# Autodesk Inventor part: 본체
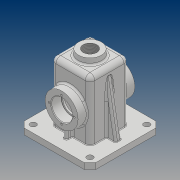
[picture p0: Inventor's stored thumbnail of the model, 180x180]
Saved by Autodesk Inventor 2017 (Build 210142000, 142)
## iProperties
Part Number: 본체
Material: 일반
Document SubType Name: Modeling
Designer: 20
Density: 1 g/cm^3
Appearance: 기본값
Mass: 292.152 g
Surface Area: 897.772 cm^2
Volume: 292.152 cm^3
Author: 20
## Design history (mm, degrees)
sketch "스케치1"
  geometry: L1 (-32.5, 32.5)-(32.5, 32.5); L2 (32.5, 32.5)-(32.5, -32.5); L3 (32.5, -32.5)-(-32.5, -32.5); L4 (-32.5, -32.5)-(-32.5, 32.5); L5 (-32.5, 32.5)-(32.5, -32.5); L6 (32.5, 32.5)-(-32.5, -32.5); 1 further point
  constraints: 12 end point, 2 midpoint, 2 parallel, 1 horizontal, 1 perpendicular
  dimensions: "d0" = 65 distance of L2.end L3.end; "d1" = 65 distance of L1.end L2.end
extrude "돌출1" new body sketch "스케치1" distance "d2" = 110; taper "d3" = 0 deg
fillet "모깎기1" dims "d4" = 8
feature "쉘1" dims "d5" = 5
sketch "스케치2"
  geometry: L1 (60, -60)-(-60, -60); L2 (-60, -60)-(-60, 60); L3 (-60, 60)-(60, 60); L4 (60, 60)-(60, -60); L5 (60, -60)-(-60, 60); L6 (-60, -60)-(60, 60); L7 (24.5, -27.5)-(-24.5, -27.5) reference; L8 (-27.5, -24.5)-(-27.5, 24.5) reference; L9 (-24.5, 27.5)-(24.5, 27.5) reference; L10 (27.5, 24.5)-(27.5, -24.5) reference; L11 (-32.5, 24.5)-(-32.5, -24.5) reference; L12 (-24.5, -32.5)-(24.5, -32.5) reference; L13 (32.5, -24.5)-(32.5, 24.5) reference; L14 (24.5, 32.5)-(-24.5, 32.5) reference; A1 r 3 centre (24.5, -24.5) between (24.5, -27.5) and (27.5, -24.5) reference; A2 r 3 centre (-24.5, -24.5) between (-27.5, -24.5) and (-24.5, -27.5) reference; A3 r 3 centre (-24.5, 24.5) between (-24.5, 27.5) and (-27.5, 24.5) reference; A4 r 3 centre (24.5, 24.5) between (27.5, 24.5) and (24.5, 27.5) reference; A5 r 8 centre (-24.5, 24.5) between (-24.5, 32.5) and (-32.5, 24.5) reference; A6 r 8 centre (-24.5, -24.5) between (-32.5, -24.5) and (-24.5, -32.5) reference; A7 r 8 centre (24.5, -24.5) between (24.5, -32.5) and (32.5, -24.5) reference; A8 r 8 centre (24.5, 24.5) between (32.5, 24.5) and (24.5, 32.5) reference; 1 further point
  constraints: 12 end point, 2 midpoint, 2 parallel, 1 horizontal, 1 perpendicular
  dimensions: "d6" = 120 distance of L2.end L3.end; "d7" = 120 distance of L1.end L2.end
extrude "돌출2" join sketch "스케치2" distance "d8" = 10; taper "d9" = 0 deg
chamfer "모따기1" distance "d10" = 10; stored, may be unused: second distance "d11" = 2, angle "d12" = 45 deg
sketch "스케치3"
  geometry: L1 (-25.5, -102)-(74.5, -102) reference; C1 r 27.5 at (24.5, -47); 2 further points
  constraints: 1 centre point, 1 midpoint, 1 vertical alignment
  dimensions: "d13" = 55 diameter of C1; "d14" = 55 distance from line of L1 C1.centre
extrude "돌출3" join sketch "스케치3" distance "d15" = 15; taper "d16" = 0 deg
sketch "스케치4"
  geometry: L1 (24.5, 47)-(24.5, 12.49) reference; L2 (-24.5, 47)-(24.5, 47) reference; L3 (-24.5, 12.49)-(-24.5, 47) reference; C1 r 17.5 at (0, 0); A1 r 27.5 centre (0, 0) between (24.5, 12.49) and (-24.5, 12.49) reference; A2 r 27.5 centre (0, 0) between (-24.5, 12.49) and (24.5, 12.49) reference; 1 further point
  constraints: 1 centre point, 1 coincident
  dimensions: "d17" = 35 diameter of C1
extrude "돌출4" cut sketch "스케치4" distance "d18" = 17; taper "d19" = 0 deg
sketch "스케치5"
  geometry: C1 r 15 at (0, 0); C2 r 17.5 at (0, 0) reference; 1 further point
  constraints: 1 centre point, 1 concentric
  dimensions: "d20" = 30 diameter of C1
extrude "돌출5" cut sketch "스케치5" distance "d21" = 3; taper "d22" = 0 deg
sketch "스케치6"
  geometry: C1 r 17.5 at (0, 0) reference; 2 further points
  constraints: 1 horizontal alignment
  dimensions: "d23" = 21 distance of C1.centre point (-21, 0)
hole "구멍1" sketch "스케치6" at (-21, 0) diameter "d24" = 3.242; stored, may be unused: countersink angle "d28" = 90 deg, drill point angle "d30" = 118 deg; dims "d25" = 8, "d26" = 4, "d27" = 2, "d29" = 10
node "작업 평면1"
sketch "스케치7"
  geometry: C1 r 20 at (0, 0); 1 further point
  constraints: 1 centre point, 1 coincident
  dimensions: "d35" = 40 diameter of C1
extrude "돌출6" join sketch "스케치7" stored distance "d36" = 10; taper "d37" = 0 deg
feature "면 기울기1" dims angle "d38" = 5 deg
hole "구멍2" diameter "d41" = 22.835; stored, may be unused: countersink angle "d45" = 90 deg, drill point angle "d47" = 118 deg; dims "d39" = 10, "d40" = 10, "d42" = 50, "d43" = 4, "d44" = 2, "d46" = 59.3
sketch "스케치8"
  geometry: L1 (-3, -27.5)-(3, -27.5); L2 (3, -27.5)-(3, -42.5); L3 (3, -42.5)-(-3, -42.5); L4 (-3, -42.5)-(-3, -27.5); L5 (-24.5, -27.5)-(24.5, -27.5) reference; 1 further point
  constraints: 8 end point, 2 parallel, 1 horizontal, 1 perpendicular
  dimensions: "d48" = 6 distance of L2.end L3.end; "d49" = 0 distance between parallel lines of L1 L5; "d50" = 3 distance from line of point (0, 0) L4; "d51" = 15 distance between parallel lines of L3 L5
extrude "돌출7" join sketch "스케치8" stored distance "d52" = 10; taper "d53" = 0 deg
sketch "스케치9"
  geometry: C1 r 5 at (-47.5, 47.5); 1 further point
  constraints: 1 centre point
  dimensions: "d54" = 10 diameter of C1; "d55" = 47.5 horizontal distance of point (0, 0) C1.centre; "d56" = 47.5 horizontal distance of point (0, 0) C1.centre
extrude "돌출8" cut sketch "스케치9" distance "d57" = 10; taper "d58" = 0 deg
sketch "스케치10"
  geometry: L1 (37.42, 70)-(48, 10); L2 (60, 10)-(50, 10) reference; L3 (-50, 10)-(50, 10) reference; L4 (60, 0)-(60, 10) reference; 1 further point
  constraints: 2 end point, 1 point on line
  dimensions: "d59" = 10 deg angle of L1 L4; "d60" = 12 distance of L1.end L2.start; "d61" = 60 vertical distance of L1.start L1.end
feature "리브1" sketch "스케치10" dims "d62" = 1, "d63" = 10, "d64" = 0, "d65" = 0, "d66" = 1, "d67" = 1
fillet "모깎기2" dims "d68" = 3
fillet "모깎기3" dims "d69" = 0.3
fillet "모깎기4" dims "d70" = 3
fillet "모깎기5" dims "d71" = 3
fillet "모깎기6" dims "d72" = 3
fillet "모깎기7" dims "d73" = 3
fillet "모깎기8" dims "d74" = 3
fillet "모깎기9" dims "d75" = 1
fillet "모깎기10" dims "d76" = 3
fillet "모깎기11" dims "d77" = 3
node "작업 평면2"
sketch "스케치11"
  geometry: L1 (57, 0)-(57, 91) reference; L2 (43.625, -18)-(5.375, -18) reference; 2 further points
  constraints: 1 other
  dimensions: "d79" = 32.5 distance from line of point (24.5, 8) L1; "d80" = 26 distance from line of point (24.5, 8) L2
feature "엠보싱1" sketch "스케치11" dims "d6" = 120, "d7" = 120, "d81" = 0.5, "d82" = 0
chamfer "모따기2" distance "d83" = 1; stored, may be unused: second distance "d84" = 2, angle "d85" = 45 deg
node "솔리드1"
mirror "미러1"
pattern_circular "원형 패턴1" dims angle "d32" = 360 deg
mirror "미러2"
mirror "미러3"
mirror "미러4"
mirror "미러5"
mirror "미러6"
node "투영된 루프1"
node "투영된 루프2"
other parameters: "d78" = 32.5
